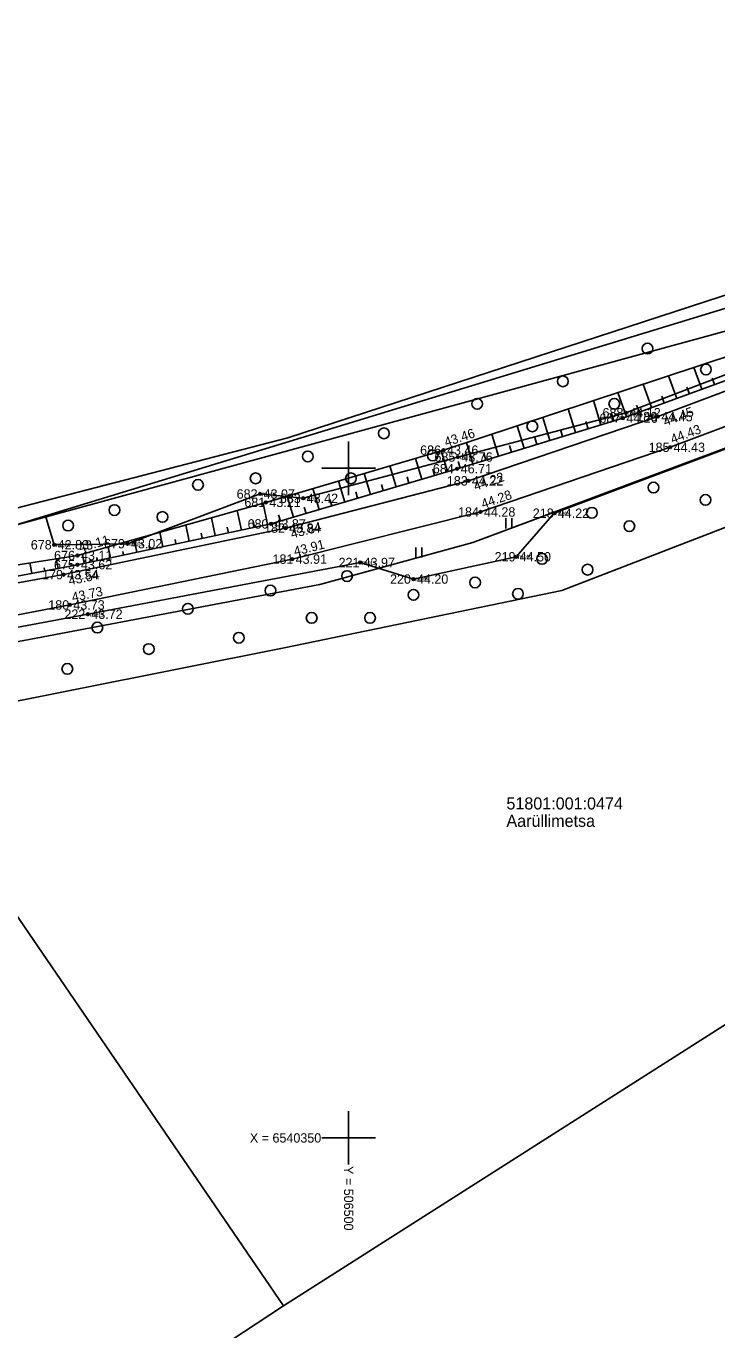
# Model space of a CAD drawing. Extents: x 505800 to 507326, y 6540058 to 6542128.
# Drawn here: x 506475.9 to 506527.5, y 6540335.7 to 6540433 of the extents above; entities that cross this region are included whole.
import ezdxf

# ---------------------------------------------------------------- set-up
doc = ezdxf.new("R2010")
doc.units = 0
for name, color, linetype in [('AED', 7, 'Continuous'), ('HALJASTUS', 7, 'Continuous'), ('KORGUS-EH2000', 7, 'Continuous'), ('MAAMUDEL', 7, 'Continuous'), ('MOOTKORG-EH2000', 7, 'Continuous'), ('MOOTMPUNKT', 7, 'Continuous'), ('MOOTNR', 7, 'Continuous'), ('MOOTPIIR', 7, 'Continuous'), ('PIIR', 7, 'Continuous'), ('RELJEEF', 7, 'Continuous'), ('TEE', 7, 'Continuous'), ('VORK', 7, 'Continuous')]:
    doc.layers.add(name, color=color, linetype=linetype)

msp = doc.modelspace()

# ---------------------------------------------------------------- linework, layer by layer
at = {"layer": 'AED'}
msp.add_lwpolyline([(506555.478, 6540425.13), (506557.144, 6540420.803), (506466.236, 6540393.054), (506460.432, 6540391.544), (506453.59, 6540403.335)], dxfattribs=at)
at = {"layer": 'HALJASTUS'}
for p, q in [((506511.736, 6540396.268), (506511.736, 6540395.507)), ((506512.191, 6540396.268), (506512.191, 6540395.507)), ((506505.01, 6540394.095), (506505.01, 6540393.334)), ((506505.465, 6540394.095), (506505.465, 6540393.334))]:
    msp.add_line(p, q, dxfattribs=at)
for points in [[(506557.354, 6540420.848), (506559.573, 6540422.003), (506560.946, 6540419.087), (506556.322, 6540416.775), (506550.153, 6540414.892), (506537.908, 6540410.713), (506520.721, 6540404.149), (506508.163, 6540400.843), (506496.611, 6540397.759), (506493.383, 6540398.082), (506483.471, 6540394.371), (506478, 6540394.292), (506477.343, 6540396.444)], [(506413.936, 6540356.957), (506411.035, 6540361.537), (506411.476, 6540364.066), (506416.66, 6540366.321), (506428.112, 6540371.138), (506442.602, 6540377.508), (506445.225, 6540379.984), (506450.028, 6540381.664), (506456.825, 6540384.191), (506464.626, 6540386.148), (506480.51, 6540389.107), (506500.858, 6540392.966), (506504.844, 6540391.729), (506512.52, 6540393.396), (506515.37, 6540396.647), (506532.173, 6540402.941), (506544.149, 6540408.028), (506554.027, 6540411.411), (506558.081, 6540412.384), (506561.957, 6540411.866), (506565.619, 6540410.412), (506569.33, 6540407.843)]]:
    msp.add_lwpolyline(points, dxfattribs=at)
for centre in [(506522.336, 6540408.939), (506526.7, 6540407.377), (506516.01, 6540406.496), (506509.605, 6540404.813), (506519.854, 6540404.813), (506513.728, 6540403.131), (506502.638, 6540402.61), (506496.953, 6540400.887), (506506.282, 6540400.962), (506493.052, 6540399.25), (506500.173, 6540399.25), (506488.745, 6540398.764), (506522.781, 6540398.562), (506482.5, 6540396.881), (506526.665, 6540397.64), (506486.086, 6540396.366), (506518.177, 6540396.679), (506479.039, 6540395.725), (506520.979, 6540395.677), (506514.453, 6540393.234), (506517.856, 6540392.432), (506499.88, 6540391.952), (506509.449, 6540391.471), (506494.155, 6540390.87), (506504.845, 6540390.55), (506512.652, 6540390.63), (506487.989, 6540389.508), (506481.223, 6540388.106), (506497.238, 6540388.827), (506501.602, 6540388.827), (506491.793, 6540387.345), (506485.066, 6540386.503), (506478.981, 6540385.021)]:
    msp.add_circle(centre, 0.4, dxfattribs=at)
at = {"layer": 'KORGUS-EH2000'}
for centre in [(506520.721, 6540404.149), (506520.494, 6540403.746), (506523.106, 6540403.859), (506507.092, 6540401.356), (506524.028, 6540401.568), (506508.163, 6540400.843), (506508.114, 6540399.97), (506508.948, 6540399.065), (506493.383, 6540398.082), (506493.818, 6540397.458), (506496.611, 6540397.759), (506509.855, 6540396.74), (506515.37, 6540396.647), (506494.198, 6540395.848), (506495.295, 6540395.538), (506478, 6540394.292), (506483.471, 6540394.371), (506479.74, 6540393.488), (506512.52, 6540393.396), (506479.734, 6540392.802), (506495.782, 6540393.218), (506500.858, 6540392.966), (506478.706, 6540392.058), (506504.844, 6540391.729), (506479.167, 6540389.797), (506480.51, 6540389.107)]:
    msp.add_circle(centre, 0.1, dxfattribs=at)
at = {"layer": 'MOOTMPUNKT'}
for centre in [(506520.721, 6540404.149), (506520.494, 6540403.746), (506523.106, 6540403.859), (506507.092, 6540401.356), (506524.028, 6540401.568), (506508.163, 6540400.843), (506508.114, 6540399.97), (506508.948, 6540399.065), (506493.383, 6540398.082), (506493.818, 6540397.458), (506496.611, 6540397.759), (506509.855, 6540396.74), (506515.37, 6540396.647), (506494.198, 6540395.848), (506495.295, 6540395.538), (506478, 6540394.292), (506483.471, 6540394.371), (506479.74, 6540393.488), (506512.52, 6540393.396), (506479.734, 6540392.802), (506495.782, 6540393.218), (506500.858, 6540392.966), (506478.706, 6540392.058), (506504.844, 6540391.729), (506479.167, 6540389.797), (506480.51, 6540389.107)]:
    msp.add_circle(centre, 0.1, dxfattribs=at)
at = {"layer": 'MOOTPIIR'}
msp.add_lwpolyline([(506461.402, 6540393.473), (506495.448, 6540402.285), (506533.638, 6540414.716), (506554.037, 6540420.685), (506555.478, 6540425.23), (506559.762, 6540425.933), (506565.047, 6540427.335), (506570.572, 6540420.725), (506573.094, 6540420.725), (506578.034, 6540411.094), (506569.01, 6540406.663), (506559.222, 6540407.565), (506515.922, 6540390.879), (506495.183, 6540386.603), (506455.807, 6540378.751)], dxfattribs=at)
at = {"layer": 'PIIR'}
for points in [[(506527.76, 6540505.12), (506563.96, 6540420.02), (506458.7, 6540391.28), (506429.21, 6540436.36), (506427.6, 6540438.79), (506466.35, 6540463.04), (506513.09, 6540491.84), (506518.32, 6540495.02), (506520.1, 6540496.45)], [(506462.8, 6540384.69), (506497.85, 6540391.32), (506509.27, 6540394.46), (506551.97, 6540410.35), (506558.26, 6540412.17), (506562.23, 6540412.5), (506566.7, 6540411.34), (506570.51, 6540407.87), (506575.14, 6540401.74), (506580.6, 6540391.81), (506495.14, 6540337.45)]]:
    msp.add_lwpolyline(points, close=True, dxfattribs=at)
for points in [[(506458.7, 6540391.28), (506563.96, 6540420.02), (506567.83, 6540420.95), (506588.42, 6540396.58), (506580.6, 6540391.81), (506575.14, 6540401.74), (506570.51, 6540407.87), (506566.7, 6540411.34), (506562.23, 6540412.5), (506558.26, 6540412.17), (506551.97, 6540410.35), (506541.41, 6540406.45), (506509.27, 6540394.46), (506497.85, 6540391.32), (506462.8, 6540384.69)], [(506224.13, 6540249.92), (506272.39, 6540267.75), (506281.65, 6540275.05), (506308, 6540301.95), (506318.07, 6540309.28), (506353.59, 6540332.53), (506374.55, 6540342.6), (506413.82, 6540364.84), (506453.27, 6540382.76), (506462.8, 6540384.69), (506495.14, 6540337.45), (506342.85, 6540237.27), (506260.72, 6540195.9), (506215.68, 6540179.69)]]:
    msp.add_lwpolyline(points, dxfattribs=at)
at = {"layer": 'RELJEEF'}
for p, q in [((506526.4, 6540405.905), (506525.805, 6540407.533)), ((506522.643, 6540404.532), (506522.004, 6540406.278)), ((506524.521, 6540405.219), (506523.905, 6540406.906)), ((506525.461, 6540405.562), (506525.279, 6540406.059)), ((506527.339, 6540406.249), (506527.164, 6540406.728)), ((506518.857, 6540403.247), (506518.304, 6540405.057)), ((506520.765, 6540403.845), (506520.104, 6540405.651)), ((506523.582, 6540404.875), (506523.394, 6540405.39)), ((506516.944, 6540402.663), (506516.405, 6540404.43)), ((506519.813, 6540403.538), (506519.646, 6540404.088)), ((506521.704, 6540404.188), (506521.509, 6540404.721)), ((506513.118, 6540401.496), (506512.605, 6540403.176)), ((506515.031, 6540402.08), (506514.505, 6540403.803)), ((506517.9, 6540402.955), (506517.736, 6540403.491)), ((506511.205, 6540400.913), (506510.706, 6540402.549)), ((506514.074, 6540401.788), (506513.918, 6540402.298)), ((506515.987, 6540402.371), (506515.827, 6540402.895)), ((506507.377, 6540399.752), (506506.917, 6540401.305)), ((506509.292, 6540400.329), (506508.806, 6540401.922)), ((506512.161, 6540401.205), (506512.009, 6540401.702)), ((506505.459, 6540399.184), (506504.998, 6540400.741)), ((506508.335, 6540400.038), (506508.191, 6540400.509)), ((506510.248, 6540400.621), (506510.1, 6540401.105)), ((506501.624, 6540398.048), (506501.16, 6540399.614)), ((506503.542, 6540398.616), (506503.079, 6540400.177)), ((506504.5, 6540398.9), (506504.362, 6540399.368)), ((506506.418, 6540399.468), (506506.28, 6540399.934)), ((506497.789, 6540396.912), (506497.322, 6540398.487)), ((506499.706, 6540397.48), (506499.241, 6540399.05)), ((506500.665, 6540397.764), (506500.526, 6540398.234)), ((506502.583, 6540398.332), (506502.444, 6540398.801)), ((506493.948, 6540395.796), (506493.611, 6540397.399)), ((506495.871, 6540396.344), (506495.403, 6540397.923)), ((506498.747, 6540397.196), (506498.608, 6540397.668)), ((506490.034, 6540394.971), (506489.752, 6540396.311)), ((506491.991, 6540395.383), (506491.681, 6540396.855)), ((506494.912, 6540396.06), (506494.772, 6540396.534)), ((506496.83, 6540396.628), (506496.69, 6540397.101)), ((506488.077, 6540394.559), (506487.823, 6540395.767)), ((506491.013, 6540395.177), (506490.924, 6540395.599)), ((506492.97, 6540395.59), (506492.873, 6540396.051)), ((506484.163, 6540393.735), (506483.964, 6540394.679)), ((506486.12, 6540394.147), (506485.893, 6540395.223)), ((506487.099, 6540394.353), (506487.026, 6540394.696)), ((506489.056, 6540394.765), (506488.975, 6540395.147)), ((506480.249, 6540392.911), (506480.106, 6540393.591)), ((506482.206, 6540393.323), (506482.035, 6540394.135)), ((506483.184, 6540393.529), (506483.129, 6540393.792)), ((506485.141, 6540393.941), (506485.078, 6540394.244)), ((506476.32, 6540392.16), (506476.175, 6540392.929)), ((506477.303, 6540392.345), (506477.261, 6540392.566)), ((506478.286, 6540392.53), (506478.152, 6540393.239)), ((506479.268, 6540392.715), (506479.23, 6540392.918)), ((506481.227, 6540393.117), (506481.18, 6540393.341))]:
    msp.add_line(p, q, dxfattribs=at)
for points in [[(506556.207, 6540417.529), (506548.446, 6540415.756), (506537.177, 6540411.287), (506507.092, 6540401.356), (506493.818, 6540397.458), (506479.74, 6540393.488), (506463.711, 6540390.977), (506454.162, 6540389.588), (506445.961, 6540387.82), (506436.644, 6540384.929), (506428.217, 6540381.232), (506425.206, 6540377.812), (506418.006, 6540373.612), (506396.112, 6540362.165), (506387.822, 6540357.514)], [(506556.207, 6540417.529), (506549.32, 6540414.59), (506538.05, 6540410.165), (506520.494, 6540403.746), (506508.114, 6540399.97), (506494.198, 6540395.848), (506479.734, 6540392.802), (506464.199, 6540389.877), (506454.62, 6540387.729), (506446.277, 6540385.845), (506437.645, 6540382.533), (506432.878, 6540380.89), (506430.375, 6540378.218), (506418.514, 6540372.235), (506396.686, 6540360.667), (506388.239, 6540356.069)]]:
    msp.add_lwpolyline(points, dxfattribs=at)
at = {"layer": 'TEE'}
for points in [[(506572.209, 6540412.1), (506567.596, 6540415.247), (506563.498, 6540416.176), (506557.625, 6540416.116), (506549.569, 6540413.859), (506538.684, 6540409.711), (506523.106, 6540403.859), (506508.948, 6540399.065), (506495.295, 6540395.538), (506478.706, 6540392.058), (506464.091, 6540389.4)], [(506570.003, 6540410.285), (506566.541, 6540412.447), (506563.041, 6540413.426), (506558.214, 6540413.286), (506550.483, 6540411.5), (506539.83, 6540407.495), (506524.028, 6540401.568), (506509.855, 6540396.74), (506495.782, 6540393.218), (506479.167, 6540389.797), (506464.651, 6540387.028)]]:
    msp.add_lwpolyline(points, dxfattribs=at)
at = {"layer": 'VORK'}
for p, q in [((506500, 6540402), (506500, 6540398)), ((506498, 6540400), (506502, 6540400)), ((506500, 6540352), (506500, 6540348)), ((506498, 6540350), (506502, 6540350))]:
    msp.add_line(p, q, dxfattribs=at)

# ---------------------------------------------------------------- texts
at = {"layer": 'KORGUS-EH2000'}
for s, rotation, p in [(' 44.45', 20.5876, (506523.414, 6540403.04)), (' 44.43', 20.56129, (506523.966, 6540401.732)), (' 43.46', 18.26744, (506507.037, 6540401.522)), (' 44.22', 18.70793, (506509.229, 6540398.236)), (' 44.28', 18.80985, (506509.799, 6540396.906)), (' 43.84', 14.48227, (506495.514, 6540394.691)), (' 43.11', 15.74879, (506479.693, 6540393.656)), (' 43.91', 14.0532, (506495.74, 6540393.388)), (' 43.54', 11.8471, (506478.886, 6540391.202)), (' 43.73', 11.63259, (506479.132, 6540389.969))]:
    msp.add_text(s, height=0.7, rotation=rotation, dxfattribs=at).set_placement(p)
for s, p in [(' 44.22', (506515.37, 6540396.297)), (' 44.50', (506512.52, 6540393.046)), (' 43.97', (506500.858, 6540392.616)), (' 44.20', (506504.844, 6540391.379)), (' 43.72', (506480.51, 6540388.757))]:
    msp.add_text(s, height=0.7, dxfattribs=at).set_placement(p)
at = {"layer": 'MAAMUDEL'}
for p in [(506520.721, 6540403.974), (506508.163, 6540400.668), (506493.383, 6540397.907), (506496.611, 6540397.584), (506515.37, 6540396.472), (506478, 6540394.117), (506483.471, 6540394.196), (506512.52, 6540393.221), (506500.858, 6540392.791), (506504.844, 6540391.554), (506480.51, 6540388.932)]:
    msp.add_text(' mets', height=0.35, dxfattribs=at).set_placement(p)
at = {"layer": 'MOOTKORG-EH2000'}
for s, p in [(' 44.26', (506520.494, 6540403.396)), (' 44.12', (506520.721, 6540403.799)), (' 44.45', (506523.106, 6540403.509)), (' 43.46', (506507.092, 6540401.006)), (' 43.76', (506508.163, 6540400.493)), (' 44.43', (506524.028, 6540401.218)), (' 46.71', (506508.114, 6540399.62)), (' 44.22', (506508.948, 6540398.715)), (' 43.07', (506493.383, 6540397.732)), (' 43.21', (506493.818, 6540397.108)), (' 43.42', (506496.611, 6540397.409)), (' 44.28', (506509.855, 6540396.39)), (' 44.22', (506515.37, 6540396.297)), (' 43.87', (506494.198, 6540395.498)), (' 43.84', (506495.295, 6540395.188)), (' 42.83', (506478, 6540393.942)), (' 43.02', (506483.471, 6540394.021)), (' 43.11', (506479.74, 6540393.138)), (' 43.91', (506495.782, 6540392.868)), (' 44.50', (506512.52, 6540393.046)), (' 43.54', (506478.706, 6540391.708)), (' 43.62', (506479.734, 6540392.452)), (' 43.97', (506500.858, 6540392.616)), (' 44.20', (506504.844, 6540391.379)), (' 43.73', (506479.167, 6540389.447)), (' 43.72', (506480.51, 6540388.757))]:
    msp.add_text(s, height=0.7, dxfattribs=at).set_placement(p)
at = {"layer": 'MOOTNR'}
for s, p in [('687 ', (506518.744, 6540403.396)), ('688 ', (506518.971, 6540403.799)), ('186 ', (506521.496, 6540403.509)), ('686 ', (506505.342, 6540401.006)), ('685 ', (506506.413, 6540400.493)), ('185 ', (506522.418, 6540401.218)), ('684 ', (506506.294, 6540399.62)), ('183 ', (506507.338, 6540398.715)), ('682 ', (506491.633, 6540397.732)), ('681 ', (506492.208, 6540397.108)), ('683 ', (506494.861, 6540397.409)), ('184 ', (506508.175, 6540396.39)), ('218 ', (506513.76, 6540396.297)), ('680 ', (506492.448, 6540395.498)), ('182 ', (506493.685, 6540395.188)), ('678 ', (506476.25, 6540393.942)), ('679 ', (506481.721, 6540394.021)), ('676 ', (506477.99, 6540393.138)), ('181 ', (506494.312, 6540392.868)), ('219 ', (506510.91, 6540393.046)), ('179 ', (506477.096, 6540391.708)), ('675 ', (506477.984, 6540392.452)), ('221 ', (506499.248, 6540392.616)), ('220 ', (506503.094, 6540391.379)), ('180 ', (506477.557, 6540389.447)), ('222 ', (506478.76, 6540388.757))]:
    msp.add_text(s, height=0.7, dxfattribs=at).set_placement(p)
at = {"layer": 'PIIR'}
for s, p in [('51801:001:0474', (506511.792, 6540374.525)), ('Aarüllimetsa', (506511.792, 6540373.225))]:
    msp.add_text(s, height=0.9, dxfattribs=at).set_placement(p)
at = {"layer": 'VORK'}
msp.add_text('X = 6540350', height=0.7, dxfattribs=at).set_placement((506492.619, 6540349.647))
msp.add_text('Y = 506500 ', height=0.7, rotation=270, dxfattribs=at).set_placement((506499.653, 6540347.897))

doc.saveas('drawing.dxf')
